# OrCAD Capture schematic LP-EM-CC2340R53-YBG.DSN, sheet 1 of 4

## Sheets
1 1_RF: size A3; title: LP-EM-CC2340R5-YBG
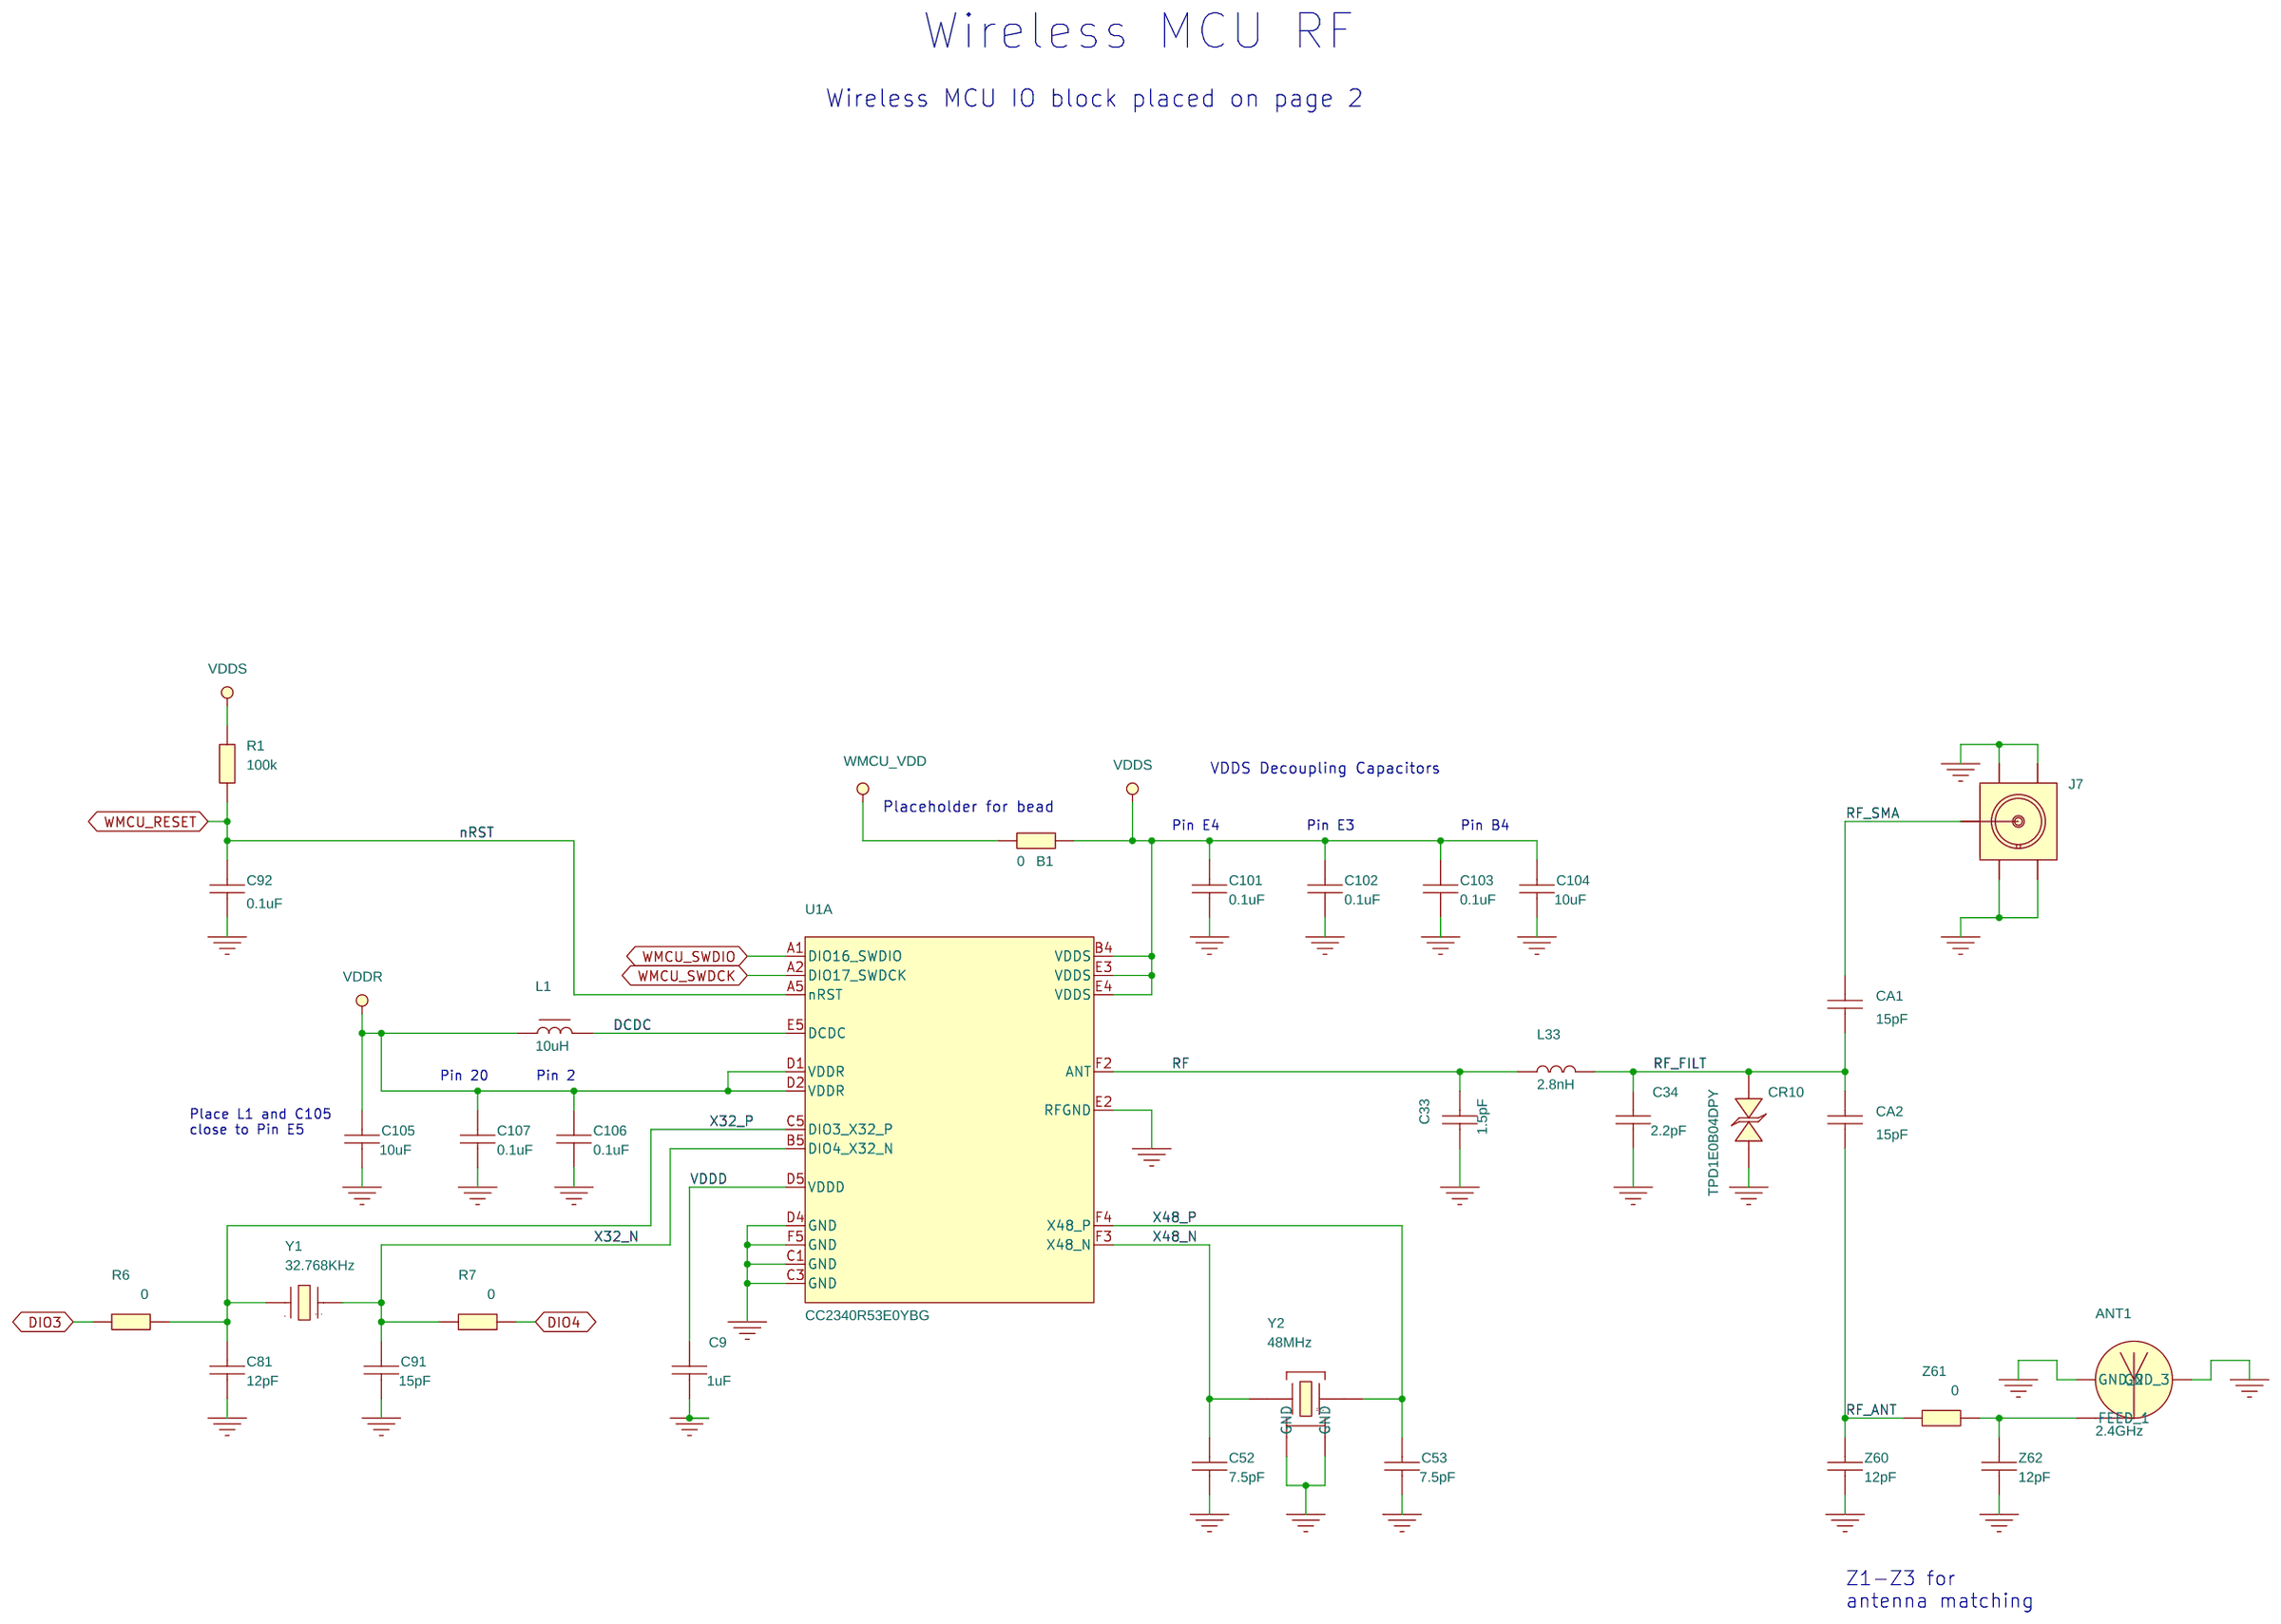
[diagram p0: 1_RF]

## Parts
sheet 1_RF
ANT1  2.4GHz  [ANTENNA_DN007AN]
B1  0  [RESC1608X55A2N]
C9  1uF  [CAPC1005X60B2N]
C33  1.5pF  [CAPC0603X35B2N]
C34  2.2pF  [CAPC0603X35B2N]
C52  7.5pF  [CAPC0603X35B2N]
C53  7.5pF  [CAPC0603X35B2N]
C81  12pF  [CAPC0603X35B2N]
C91  15pF  [CAPC0603X35B2N]
C92  0.1uF  [CAPC0603X35B2N]
C101  0.1uF  [CAPC0603X35B2N]
C102  0.1uF  [CAPC0603X35B2N]
C103  0.1uF  [CAPC0603X35B2N]
C104  10uF  [CAPC1608X100A2N]
C105  10uF  [CAPC1608X100A2N]
C106  0.1uF  [CAPC0603X35B2N]
C107  0.1uF  [CAPC0603X35B2N]
CA1  15pF  [CAPC0603X35B2N]
CA2  15pF  [CAPC0603X35B2N]
CR10  TPD1E0B04DPY  [SON65P100X60X45-2A2N]
J7  SMA-10V21-TGG  [HUSTSAN_SMA10V21TGGAN]
L1  10uH  [INDC1608X100A2N]
L33  2.8nH  [INDC0603X33A2N]
R1  100k  [RESC0603X35B2N]
R6  0  [RESC0603X35B2N]
R7  0  [RESC0603X35B2N]
Y1  32.768KHz  [XTAL_TZ3359DAAO73_A2N]
Y2  48MHz  [OSCCC205X165X50-4A2N]
Z60  12pF  [CAPC0603X35B2N]
Z61  0  [RESC0603X35B2N]
Z62  12pF  [CAPC0603X35B2N]
sheet 2_Peripherals
U1  CC2340R53E0YBG  [BGAFC28C40P260X219X50]  (sections A,B)

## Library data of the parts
ANT1 = ANTENNA_DN007: ANTENNA, NON COMPONENT, 2.4GHz INVERTED F ANTENNA, NOT APPLY; Additional Datasheet URL: https://www.ti.com/; AutoDoc File: http://notefied-dynamic-precision.com/DB/Apps/Desktop/Item/Object.aspx?id=85542; Budget Currency: N/A; Budget Price: N/A; CLASS: DISCRETE; Country of Origin: Missing Info; Datasheet URL: N/A; Datasheet URL 1: http://www.ti.com/lit/er/swrz002d/swrz002d.pdf; Datasheet URL 2: http://www.ti.com/lit/ds/symlink/cc2500.pdf; Definied Quality: INDUSTRIAL; Esd Level: HBM 500V; FPLIST: ANTENNA_DN007N,ANTENNA_DN007AN,; MPN: DN007; MPN Status: ACTIVE; MSL: N/A; MTBF: N/A; MTBF Standard: N/A; Manufacturer: TEXAS INSTRUMENTS; Mass: N/A; Max Oper Temp: +85DEGC; Maximum Operating Temperature: +85DEGC; Min Oper Temp: -40DEGC; Minimum Operating Temperature: -40DEGC; Mounting Type: NOT APPLY; NOTE Status: PREFERRED; NOTEfied URL: https://dev-webinterface.dpserver.no/item/7337272; Notes: Custom Item; Old Footprint: ANTENNA_DN007N,ANTENNA_DN007AN; Packing Size: N/A; Packing Type: Missing Info; Part Number: 13-00347; Part Type: Mechanic|ANTENNA|NON COMPONENT; ROHS: Not Applicable; Revision: R029; RoHS Status: LEADED; Status: Released; Texas Part Status: Under Review; Type: Mechanic; Vendor: TEXAS INSTRUMENTS; Vendor Part Number: DN007; Vendor Part Status: Active; WEIGHT: N/A
B1 = RESISTOR: RESISTOR, THICK FILM, JUMPER, 0, 0R/+0.05R, 1A, -55DEGC/+155DEGC, 0603, SMD; ALT_SYMBOLS: RESC1608X55A2L,RESC1608X55A2M; Additional Datasheet URL: https://www.koaspeer.com/products/resistors/general-purpose/rk73z/; Budgetary Price: .003 EUR; Country of Origin: China, Japan, Malaysia; Datasheet URL: https://www.koaspeer.com/pdfs/RK73Z.pdf; Lead Time: 46; Mass: 0.00214g; Maximum Operating Temperature: +155DEGC; Maximum Temperature Coefficient: N/A; Maximum Tolerance: +0.05R; Minimum Operating Temperature: -55DEGC; Minimum Temperature Coefficient: N/A; Minimum Temperature Coeficient: N/A; Minimum Tolerance: 0R; Mounting Type: SMD; NOTEfied URL: https://dev-webinterface.dpserver.no/item/7187910; PCB Package: 0603; Packing Size: 5000; Packing Type: Tape & Reel; Part Number: 01-01788; Part Type: Resistor|0603|JUMPER; ROHS: Exempt; Rated Current: 1A; Rated Power: 0.1; Rated Voltage: N/A; Resistor Type: THICK FILM; Revision: R048; Status: Released; Type: Resistor; Vendor: KOA SPEER; Vendor Part Number: RK73Z1JTTD; Vendor Part Status: Active
C9 = CAPACITOR: CAPACITOR, CERAMIC X7R, 1uF, 10V, -10%/+10%, -55DEGC/+125DEGC, 0402, SMD; ALT_SYMBOLS: CAPC1005X60A2L,CAPC1005X60A2M; Additional Datasheet URL: https://www.murata.com/en-us/products/productdetail?partno=GRM155Z71A105KE01%23; Budgetary Price: .01649 EUR; Country of Origin: China, Japan, Philippines, Singapore, Thailand; Datasheet URL: https://search.murata.co.jp/Ceramy/image/img/A01X/G101/ENG/GRM155Z71A105KE01-01A.pdf; Dielectric Type: X7R; Mass: 0.0016g; Maximum Operating Temperature: +125DEGC; Maximum Tolerance: +10%; Minimum Operating Temperature: -55DEGC; Minimum Tolerance: -10%; Mounting Type: SMD; NOTEfied URL: https://dev-webinterface.dpserver.no/item/34840285; PCB Package: 0402; Packing Size: 10000; Packing Type: Tape & Reel; Part Number: 02-10417; Part Type: Capacitor|CERAMIC|0402|STANDARD; REACH/SVHC Compliance: Compliant; REACH/SVHC Details: SVHC List Version Jul 08, 2021; REACH/SVHC Source: REACH Declaration; REACH/SVHC Status: Unaffected; ROHS: Compliant; Rated Voltage: 10V; Revision: R002; Status: Released; Texas Part Status: Under Review; Type: Capacitor; Vendor: MURATA; Vendor Part Number: GRM155Z71A105KE01D; Vendor Part Status: Active
C33 = CAPACITOR: CAPACITOR, CERAMIC C0G/NP0, 1.5pF, 50V, -0.1pF/+0.1pF, -55DEGC/+125DEGC, 0201, SMD; ALT_SYMBOLS: CAPC0603X35B2L,CAPC0603X35B2M; Additional Datasheet URL: https://www.murata.com/en-us/products/productdetail?partno=GRM0335C1H1R5BA01%23; AutoDoc File: https://notefied-dynamic-precision.com/DB/Apps/Desktop/Item/Object.aspx?id=113355; BU Name: TEXAS INSTRUMENTS NORWAY; Budget Currency: EUR; Budget Price: 0.006; Budgetary Price: .00272 USD; Country of Origin: China, Japan, Philippines; Datasheet URL: https://search.murata.co.jp/Ceramy/image/img/A01X/G101/ENG/GRM0335C1H1R5BA01-01A.pdf; Datasheet URL 1: http://psearch.murata.com/capacitor/product/GRM1555C1H1R0CA01%23.pdf; Datasheet URL 2: http://search.murata.co.jp/Ceramy/image/img/w_hinm/L0005E.pdf; Dielectric Type: C0G/NP0; Lead Time: 11; MPN: GRM1555C1H1R0CA01D; MPN Status: ACTIVE; Manufacturer: MURATA; Mass: 0.00033g; Max Oper Temp: +125DEGC; Max Tol: +0.25pF; Maximum Operating Temperature: +125DEGC; Maximum Tolerance: +0.1pF; Min Oper Temp: -55DEGC; Min Tol: -0.25pF; Minimum Operating Temperature: -55DEGC; Minimum Tolerance: -0.1pF; Mounting Type: SMD; NOTE Status: PREFERRED; NOTEfied URL: https://dev-webinterface.dpserver.no/item/7272572; Old Footprint: CAPC1005X60N; PCB Package: 0201; Packing Size: 50000; Packing Type: Tape & Reel; Part Number: 02-06129; Part Type: Capacitor|CERAMIC|0201|STANDARD; REACH/SVHC Compliance: Compliant; REACH/SVHC Details: SVHC List Version Jul 7, 2017; REACH/SVHC Source: REACH Declaration; REACH/SVHC Status: Unaffected; REACH/SVHC_COMPLIANCE: COMPLIANT; REACH/SVHC_DETAILS: SVHC LIST VERSION Dec 17, 2015; REACH/SVHC_SOURCE: REACH DECLARATION; REACH/SVHC_STATUS: UNAFFECTED; ROHS: Compliant; Rated Voltage: 50V; Revision: R027; RoHS Status: ROHS_COMPLIANT; Rtd Voltage: 50V; Status: Released; Texas Part Status: Under Review; Type: Capacitor; Vendor: MURATA; Vendor Part Number: GRM0335C1H1R5BA01J; Vendor Part Status: Active; WEIGHT: 0.0016g
C34 = CAPACITOR: CAPACITOR, CERAMIC C0G/NP0, 2.2pF, -0.1pF/+0.1pF, 50V, -55DEGC/+125DEGC, 0201, SMD; ALT_SYMBOLS: CAPC0603X35B2L,CAPC0603X35B2M; Additional Datasheet URL: https://pim.murata.com/en-us/pim/details?partNum=GRM0335C1H2R2BA01%23; Budgetary Price: .00272 USD; Country of Origin: China, Japan, Philippines, Singapore, Thailand; Datasheet URL: https://pim.murata.com/asset/pim4/ceramicCapacitorSMD/GRM0335C1H2R2BA01-01A-EN_PDF_CERAMICCAPACITORSMD?lastModifiedDatetime=20250813140605; Dielectric Type: C0G/NP0; Lead Time: 11; Mass: 0.00033g; Maximum Operating Temperature: +125DEGC; Maximum Tolerance: +0.1pF; Minimum Operating Temperature: -55DEGC; Minimum Tolerance: -0.1pF; Mounting Type: SMD; NOTEfied URL: https://webinterface.notefied-dynamic-precision.com/item/7272864; PCB Package: 0201; Packing Size: 50000; Packing Type: Tape & Reel; Part Number: 02-06136; Part Type: Capacitor|CERAMIC|0201|STANDARD; REACH/SVHC Compliance: Compliant; REACH/SVHC Details: SVHC List Version Jan 23, 2024 (240); REACH/SVHC Source: REACH Declaration; REACH/SVHC Status: Unaffected; ROHS: Compliant; Rated Voltage: 50V; Status: Released; Texas Part Status: Under Review; Type: Capacitor; Vendor: MURATA; Vendor Part Number: GRM0335C1H2R2BA01J; Vendor Part Status: Active
C52 C53 = CAPACITOR: CAPACITOR, CERAMIC C0G/NP0, 7.5pF, 50V, -0.1pF/+0.1pF, -55DEGC/+125DEGC, 0201, SMD; ALT_SYMBOLS: CAPC0603X35B2L,CAPC0603X35B2M; Additional Datasheet URL: https://www.murata.com/en-us/products/productdetail?partno=GRM0335C1H7R5BA01%23; Budgetary Price: .00221 USD; Country of Origin: China, Japan, Philippines; Datasheet URL: https://search.murata.co.jp/Ceramy/image/img/A01X/G101/ENG/GRM0335C1H7R5BA01-01A.pdf; Dielectric Type: C0G/NP0; Lead Time: 11; Mass: 0.00033g; Maximum Operating Temperature: +125DEGC; Maximum Tolerance: +0.1pF; Minimum Operating Temperature: -55DEGC; Minimum Tolerance: -0.1pF; Mounting Type: SMD; NOTEfied URL: https://dev-webinterface.dpserver.no/item/7272937; PCB Package: 0201; Packing Size: 50000; Packing Type: Tape & Reel; Part Number: 02-06189; Part Type: Capacitor|CERAMIC|0201|STANDARD; REACH/SVHC Compliance: Compliant; REACH/SVHC Details: SVHC List Version Jul 7, 2017; REACH/SVHC Source: REACH Declaration; REACH/SVHC Status: Unaffected; ROHS: Compliant; Rated Voltage: 50V; Revision: R027; Status: Released; Texas Part Status: Under Review; Type: Capacitor; Vendor: MURATA; Vendor Part Number: GRM0335C1H7R5BA01J; Vendor Part Status: Active
C81 = CAPACITOR: CAPACITOR, CERAMIC C0G/NP0, 12pF, 50V, -2%/+2%, -55DEGC/+125DEGC, 0201, SMD; ALT_SYMBOLS: CAPC0603X35B2L,CAPC0603X35B2M; Additional Datasheet URL: https://www.murata.com/en-us/products/productdetail?partno=GRM0335C1H120GA01%23; AutoDoc File: https://notefied-dynamic-precision.com/DB/Apps/Desktop/Item/Object.aspx?id=113345; BU Name: TEXAS INSTRUMENTS NORWAY; Budget Currency: EUR; Budget Price: 0.007; Budgetary Price: .00506 USD; Country of Origin: China, Japan, Philippines; Datasheet URL: https://search.murata.co.jp/Ceramy/image/img/A01X/G101/ENG/GRM0335C1H120GA01-01A.pdf; Datasheet URL 1: http://psearch.murata.com/capacitor/product/GRM1555C1H120JA01%23.pdf; Datasheet URL 2: http://search.murata.co.jp/Ceramy/image/img/w_hinm/L0005E.pdf; Definied Quality: INDUSTRIAL; Dielectric Type: C0G/NP0; Esd Level: N/A; Lead Time: 23; LifeCycle Status: ACTIVE; MPN: CAPACITOR_0402_12pF_C0G/NP0_M_+/-5%_50V; MPN Status: ACTIVE; MSL: N/A; MTBF: N/A; MTBF Standard: N/A; Manufacturer: MANUFACTURER SELECTION; Mass: 0.00033g; Max Oper Temp: +125DEGC; Max Tol: +5%; Maximum Operating Temperature: +125DEGC; Maximum Tolerance: +2%; Min Oper Temp: -55DEGC; Min Tol: -5%; Minimum Operating Temperature: -55DEGC; Minimum Tolerance: -2%; Mounting Type: SMD; NOTE Status: PREFERRED; NOTEfied URL: https://dev-webinterface.dpserver.no/item/31254676; Old Footprint: CAPC1005X60N; PCB Package: 0201; Packing Size: 15000; Packing Type: Tape & Reel; Part Number: 02-10307; Part Type: Capacitor|CERAMIC|0201|STANDARD; REACH/SVHC Compliance: Compliant; REACH/SVHC Details: SVHC List Version Jan 19, 2021; REACH/SVHC Source: REACH Declaration; REACH/SVHC Status: Unaffected; REACH/SVHC_COMPLIANCE: COMPLIANT; REACH/SVHC_DETAILS: SVHC LIST VERSION Dec 17, 2015; REACH/SVHC_SOURCE: REACH DECLARATION; REACH/SVHC_STATUS: UNAFFECTED; ROHS: Compliant; Rated Voltage: 50V; Revision: R003; RoHS Status: ROHS_COMPLIANT; Rtd Voltage: 50V; Status: Released; Texas Part Status: Under Review; Type: Capacitor; Vendor: MURATA; Vendor Part Number: GRM0335C1H120GA01D; Vendor Part Status: Active; WEIGHT: 0.0016g
C91 = CAPACITOR: CAPACITOR, CERAMIC C0G/NP0, 15pF, 50V, -2%/+2%, -55DEGC/+125DEGC, 0201, SMD; ALT_SYMBOLS: CAPC0603X35B2L,CAPC0603X35B2M; Additional Datasheet URL: https://www.murata.com/en-us/products/productdetail?partno=GRM0335C1H150GA01%23; AutoDoc File: https://notefied-dynamic-precision.com/DB/Apps/Desktop/Item/Object.aspx?id=114571; BU Name: TEXAS INSTRUMENTS NORWAY; Budget Currency: EUR; Budget Price: 0.006; Budgetary Price: .0032 USD; Client Status: UNDER_REVIEW; Country of Origin: China, Japan, Philippines; Datasheet URL: https://search.murata.co.jp/Ceramy/image/img/A01X/G101/ENG/GRM0335C1H150GA01-01A.pdf; Datasheet URL 1: http://psearch.murata.com/capacitor/product/GRM1555C1H150JA01%23.pdf; Datasheet URL 2: http://psearch.en.murata.com/capacitor/product/GRM1555C1H150JA01%23.html; Definied Quality: INDUSTRIAL; Dielectric Type: C0G/NP0; Esd Level: N/A; Lead Time: 11; LifeCycle Status: ACTIVE; MPN: CAPACITOR_0402_12pF_C0G/NP0_M_+/-5%_50V; MPN Status: ACTIVE; MSL: N/A; MTBF: N/A; MTBF Standard: N/A; Manufacturer: MANUFACTURER SELECTION; Mass: 0.00033g; Max Oper Temp: +125DEGC; Max Tol: +5%; Maximum Operating Temperature: +125DEGC; Maximum Tolerance: +2%; Min Oper Temp: -55DEGC; Min Tol: -5%; Minimum Operating Temperature: -55DEGC; Minimum Tolerance: -2%; Mounting Type: SMD; NOTE Status: PREFERRED; NOTEfied URL: https://dev-webinterface.dpserver.no/item/20744949; Old Footprint: CAPC1005X60N; PCB Package: 0201; Packing Size: 15000; Packing Type: Tape & Reel; Part Number: 02-09323; Part Type: Capacitor|CERAMIC|0201|STANDARD; REACH/SVHC Compliance: Compliant; REACH/SVHC Details: SVHC List Version Jan 15, 2019; REACH/SVHC Source: REACH Declaration; REACH/SVHC Status: Unaffected; REACH/SVHC_COMPLIANCE: COMPLIANT; REACH/SVHC_DETAILS: SVHC List Version Jan 12, 2017; REACH/SVHC_SOURCE: REACH DECLARATION; REACH/SVHC_STATUS: UNAFFECTED; ROHS: Compliant; Rated Voltage: 50V; Revision: R010; RoHS Status: ROHS_COMPLIANT; Rtd Voltage: 50V; Status: Released; Texas Part Status: Under Review; Type: Capacitor; Vendor: MURATA; Vendor Part Number: GRM0335C1H150GA01D; Vendor Part Status: Active; WEIGHT: 0.0016g
C92 C101-C103 C106 C107 = CAPACITOR: CAPACITOR, CERAMIC X7S, 0.1uF, 10V, -10%/+10%, -55DEGC/+125DEGC, 0201, SMD; ALT_SYMBOLS: CAPC0603X35B2L,CAPC0603X35B2M; Additional Datasheet URL: https://www.murata.com/en-us/products/productdetail?partno=GRM033C71A104KE14%23; AutoDoc File: https://notefied-dynamic-precision.com/DB/Apps/Desktop/Item/Object.aspx?id=115293; BU Name: TEXAS INSTRUMENTS NORWAY; Budgetary Price: .01328 USD; Client Status: UNDER_REVIEW; Country of Origin: China, Japan, Philippines, Singapore; Datasheet URL: https://search.murata.co.jp/Ceramy/image/img/A01X/G101/ENG/GRM033C71A104KE14-01A.pdf; Datasheet URL 1: http://psearch.en.murata.com/capacitor/product/GRM155R71E104KE14%23.pdf; Datasheet URL 2: http://search.murata.co.jp/Ceramy/image/img/w_hinm/L0005E.pdf; Dielectric Type: X7S; Lead Time: 23; LifeCycle Status: ACTIVE; MPN: GRM155R70J104KA01D; MPN Status: ACTIVE; Manufacturer: MURATA; Mass: 0.00033g; Max Oper Temp: +125DEGC; Max Tol: +10%; Maximum Operating Temperature: +125DEGC; Maximum Tolerance: +10%; Min Oper Temp: -55DEGC; Min Tol: -10%; Minimum Operating Temperature: -55DEGC; Minimum Tolerance: -10%; Mounting Type: SMD; NOTE Status: PREFERRED; NOTEfied URL: https://dev-webinterface.dpserver.no/item/31254761; Old Footprint: CAPC1005X60N,0402; PCB Package: 0201; Packing Size: 15000; Packing Type: Tape & Reel; Part Number: 02-10308; Part Type: Capacitor|CERAMIC|0201|STANDARD; REACH/SVHC Compliance: Compliant; REACH/SVHC Details: SVHC List Version Jan 19, 2021; REACH/SVHC Source: REACH Declaration; REACH/SVHC Status: Unaffected; REACH/SVHC_COMPLIANCE: COMPLIANT; REACH/SVHC_DETAILS: SVHC LIST VERSION Jun 20, 2016; REACH/SVHC_SOURCE: REACH DECLARATION; REACH/SVHC_STATUS: UNAFFECTED; ROHS: Compliant; Rated Voltage: 10V; Revision: R003; RoHS Status: ROHS_COMPLIANT; Rtd Voltage: 25V; Status: Released; Texas Part Status: Under Review; Type: Capacitor; Vendor: MURATA; Vendor Part Number: GRM033C71A104KE14D; Vendor Part Status: Active; WEIGHT: 0.0016g
C104 C105 = CAPACITOR: CAPACITOR, CERAMIC X7R, 10uF, 10V, -10%/+10%, -55DEGC/+125DEGC, 0603, SMD; ALT_SYMBOLS: CAPC1608X100A2L,CAPC1608X100A2M; Additional Datasheet URL: https://www.murata.com/en-us/products/productdetail?partno=GRM188Z71A106KA73%23; Budgetary Price: .05362 EUR; Country of Origin: China, Japan, Philippines; Datasheet URL: https://search.murata.co.jp/Ceramy/image/img/A01X/G101/ENG/GRM188Z71A106KA73-01A.pdf; Dielectric Type: X7R; Mass: 0.0091g; Maximum Operating Temperature: +125DEGC; Maximum Tolerance: +10%; Minimum Operating Temperature: -55DEGC; Minimum Tolerance: -10%; Mounting Type: SMD; NOTEfied URL: https://dev-webinterface.dpserver.no/item/34840340; PCB Package: 0603; Packing Size: 4000; Packing Type: Tape & Reel; Part Number: 02-10418; Part Type: Capacitor|CERAMIC|0603|STANDARD; REACH/SVHC Compliance: Compliant; REACH/SVHC Details: SVHC List Version Jul 08, 2021; REACH/SVHC Source: REACH Declaration; REACH/SVHC Status: Unaffected; ROHS: Compliant; Rated Voltage: 10V; Revision: R002; Status: Released; Texas Part Status: Under Review; Type: Capacitor; Vendor: MURATA; Vendor Part Number: GRM188Z71A106KA73D; Vendor Part Status: Active
CA1 CA2 = CAPACITOR: CAPACITOR, CERAMIC C0G/NP0, 15pF, 50V, -2%/+2%, -55DEGC/+125DEGC, 0201, SMD; ALT_SYMBOLS: CAPC0603X35B2L,CAPC0603X35B2M; Additional Datasheet URL: https://www.murata.com/en-us/products/productdetail?partno=GRM0335C1H150GA01%23; AutoDoc File: https://notefied-dynamic-precision.com/DB/Apps/Desktop/Item/Object.aspx?id=113345; BU Name: TEXAS INSTRUMENTS NORWAY; Budget Currency: EUR; Budget Price: 0.007; Budgetary Price: .0032 USD; Country of Origin: China, Japan, Philippines; Datasheet URL: https://search.murata.co.jp/Ceramy/image/img/A01X/G101/ENG/GRM0335C1H150GA01-01A.pdf; Datasheet URL 1: http://psearch.murata.com/capacitor/product/GRM1555C1H120JA01%23.pdf; Datasheet URL 2: http://search.murata.co.jp/Ceramy/image/img/w_hinm/L0005E.pdf; Definied Quality: INDUSTRIAL; Dielectric Type: C0G/NP0; Esd Level: N/A; Lead Time: 11; LifeCycle Status: ACTIVE; MPN: CAPACITOR_0402_12pF_C0G/NP0_M_+/-5%_50V; MPN Status: ACTIVE; MSL: N/A; MTBF: N/A; MTBF Standard: N/A; Manufacturer: MANUFACTURER SELECTION; Mass: 0.00033g; Max Oper Temp: +125DEGC; Max Tol: +5%; Maximum Operating Temperature: +125DEGC; Maximum Tolerance: +2%; Min Oper Temp: -55DEGC; Min Tol: -5%; Minimum Operating Temperature: -55DEGC; Minimum Tolerance: -2%; Mounting Type: SMD; NOTE Status: PREFERRED; NOTEfied URL: https://dev-webinterface.dpserver.no/item/20744949; Old Footprint: CAPC1005X60N; PCB Package: 0201; Packing Size: 15000; Packing Type: Tape & Reel; Part Number: 02-09323; Part Type: Capacitor|CERAMIC|0201|STANDARD; REACH/SVHC Compliance: Compliant; REACH/SVHC Details: SVHC List Version Jan 15, 2019; REACH/SVHC Source: REACH Declaration; REACH/SVHC Status: Unaffected; REACH/SVHC_COMPLIANCE: COMPLIANT; REACH/SVHC_DETAILS: SVHC LIST VERSION Dec 17, 2015; REACH/SVHC_SOURCE: REACH DECLARATION; REACH/SVHC_STATUS: UNAFFECTED; ROHS: Compliant; Rated Voltage: 50V; Revision: R010; RoHS Status: ROHS_COMPLIANT; Rtd Voltage: 50V; Status: Released; Texas Part Status: Under Review; Type: Capacitor; Vendor: MURATA; Vendor Part Number: GRM0335C1H150GA01D; Vendor Part Status: Active; WEIGHT: 0.0016g
CR10 = DIODE_TVS_BIDIR_S_0: DIODE, PROTECTION, TVS, BID, 6.7V, 15W, -40DEGC/+125DEGC, X1SON2, SMD; Additional Datasheet URL: https://www.ti.com/product/TPD1E0B04; AutoDoc File: https://notefied-dynamic-precision.com/DB/Apps/Desktop/Item/Object.aspx?id=118028; BU Name: DYNAMIC PRECISION GDANSK; Budget Currency: USD; Budget Price: 0.08; Budgetary Price: .144 USD; Client Status: UNDER_REVIEW; Country of Origin: China; Datasheet URL: https://www.ti.com/lit/gpn/TPD1E0B04; Datasheet URL 1: http://www.ti.com/lit/ds/symlink/tpd1e0b04.pdf; Datasheet URL 2: http://www.ti.com/lit/ml/mpss034c/mpss034c.pdf; Lead Time: 12; Mass: 0.0031g; Max Oper Temp: +125DEGC; Maximum Operating Temperature: +125DEGC; Min Oper Temp: -40DEGC; Minimum Operating Temperature: -40DEGC; Mounting Type: SMD; NOTEfied URL: https://dev-webinterface.dpserver.no/item/12481442; PCB Package: SON2; Packing Size: 10000; Packing Type: Tape & Reel; Part Number: 14-06704; Part Type: Diode|PROTECTION; REACH/SVHC Compliance: Compliant; REACH/SVHC Details: SVHC List Version Jan 12, 2017; REACH/SVHC Source: REACH Declaration; REACH/SVHC Status: Unaffected; ROHS: Compliant; Rated Power: 15W; Rated Voltage: 6.7V; Revision: R025; RoHS Status: ROHS_COMPLIANT; Rtd Power: 15W; Rtd Voltage: 6.7V; Status: Released; Texas Part Status: Under Review; Type: Diode; Vendor: TEXAS INSTRUMENTS; Vendor Part Number: TPD1E0B04DPYR; Vendor Part Status: Active; Weight: 0.0031g
J7 = CONN_COAX_1_4: CONNECTOR, COAX, RF, FEMALE, STRAIGHT, 1 PIN(S), SMD; ALT_SYMBOLS: HUSTSAN_SMA10V21TGGL,HUSTSAN_SMA10V21TGGM; Additional Datasheet URL: http://www.hustsan.com.tw/cgi-bin/productfn/pdt_detail_lst.pl?ProdID=143; AutoDoc File: https://notefied-dynamic-precision.com/DB/Apps/Desktop/Item/Object.aspx?id=84956; BU Name: DYNAMIC PRECISION GDANSK; Budget Currency: N/A; Budget Price: N/A; Client Status: UNDER_REVIEW; Country of Origin: Missing Info; Datasheet URL: http://www.hustsan.com.tw/uploaddir/product/SMA-10V21.pdf; Datasheet URL 1: http://www.hustsan.com.tw/uploaddir/product/SMA-10V21.pdf; Datasheet URL 2: http://www.hustsan.com.tw/cgi-bin/productfn/pdt_detail_lst.pl?ProdID=143; FPLIST: HUSTSAN_SMA10V21TGGAN,HUSTSAN_SMA10V21TGGN; Mass: N/A; Mounting Type: SMD; NOTEfied URL: https://dev-webinterface.dpserver.no/item/7315189; No Of Pos: 1; Number of Positions: 1; Packing Size: 350; Packing Type: Tape & Reel; Part Number: 06-02188; Part Type: Connector|COAX|RF; REACH/SVHC Compliance: Compliant; REACH/SVHC Details: SVHC List Version Jun 20, 2016; REACH/SVHC Source: REACH Declaration; REACH/SVHC Status: Unaffected; REACH/SVHC_COMPLIANCE: COMPLIANT; REACH/SVHC_DETAILS: SVHC LIST VERSION Jan 12, 2016; REACH/SVHC_SOURCE: REACH DECLARATION; REACH/SVHC_STATUS: UNAFFECTED; ROHS: Compliant; Revision: R024; RoHS Status: ROHS_COMPLIANT; Status: Released; Texas Part Status: Under Review; Type: Connector; Vendor: HUS-TSAN; Vendor Part Status: Active; Weight: N/A
L1 = IND_CORE: INDUCTOR, STANDARD, CHIP, FERRITE CORE, 10uH, -20%/+20%, 0.1A, -55DEGC/+125DEGC, 0603, SMD; ALT_SYMBOLS: INDC1608X100A2L,INDC1608X100A2M; Additional Datasheet URL: https://www.murata.com/en-us/products/productdetail?partno=LQM18DN100M70%23; Budgetary Price: .02994 USD; Country of Origin: Missing Info; Datasheet URL: https://search.murata.co.jp/Ceramy/image/img/P02/JELF243B-0086.pdf; Frequency: 32MHz; Mass: 0.005g; Maximum Operating Temperature: +125DEGC; Maximum Tolerance: +20%; Minimum Operating Temperature: -55DEGC; Minimum Tolerance: -20%; Mounting Type: SMD; NOTEfied URL: https://dev-webinterface.dpserver.no/item/34987006; PCB Package: 0603; Packing Size: 4000; Packing Type: Tape & Reel; Part Number: 03-08367; Part Type: Inductor|STANDARD|CHIP|0603; REACH/SVHC Compliance: Missing Info; REACH/SVHC Details: Jul 08, 2021 (219); REACH/SVHC Source: N/A; REACH/SVHC Status: Unaffected; ROHS: Compliant; Rated Current: 0.1A; Resistance: 1.05; Revision: R002; Status: Released; Texas Part Status: Under Review; Type: Inductor; Vendor: MURATA; Vendor Part Number: LQM18DN100M70L; Vendor Part Status: Active
L33 = INDUCTOR: INDUCTOR, RF, CHIP, NON-MAGNETIC CORE, 2.8nH, -0.1nH/+0.1nH, 0.5A, -55DEGC/+125DEGC, 0201, SMD; ALT_SYMBOLS: INDC0603X33A2L,INDC0603X33A2M; Additional Datasheet URL: https://www.murata.com/en-us/products/productdetail?partno=LQP03TN2N8B02%23; Country of Origin: Missing Info; Datasheet URL: https://search.murata.co.jp/Ceramy/image/img/P02/JELF243C-0015.pdf; Frequency: 9.5GHz; Mass: 0.0002g; Maximum Operating Temperature: +125DEGC; Maximum Tolerance: +0.1nH; Minimum Operating Temperature: -55DEGC; Minimum Tolerance: -0.1nH; Mounting Type: SMD; NOTEfied URL: https://dev-webinterface.dpserver.no/item/7300385; PCB Package: 0201; Packing Size: 50000; Packing Type: Tape & Reel; Part Number: 03-06931; Part Type: Inductor|RF|CHIP|0201; ROHS: Compliant; Rated Current: 0.5A; Resistance: 0.2; Revision: R022; Status: Released; Texas Part Status: Under Review; Type: Inductor; Vendor: MURATA; Vendor Part Number: LQP03TN2N8B02J; Vendor Part Status: Active
R1 = RESISTOR: RESISTOR, THICK FILM, 100k, -5%/+5%, 0.05W, 30V, -55DEGC/+155DEGC, 0201, SMD; ALT_SYMBOLS: RESC0603X35B2L,RESC0603X35B2M; Additional Datasheet URL: https://www.vishay.com/en/product/20052/; Budgetary Price: .005 EUR; Country of Origin: China, Israel, Taiwan; Datasheet URL: https://www.vishay.com/docs/20052/crcw0201e3.pdf; Lead Time: 20; Mass: 0.00017g; Maximum Operating Temperature: +155DEGC; Maximum Temperature Coefficient: +200PPM/DEGC; Maximum Tolerance: +5%; Minimum Operating Temperature: -55DEGC; Minimum Temperature Coefficient: -200PPM/DEGC; Minimum Temperature Coeficient: -200PPM/DEGC; Minimum Tolerance: -5%; Mounting Type: SMD; NOTEfied URL: https://dev-webinterface.dpserver.no/item/7195810; PCB Package: 0201; Packing Size: 10000; Packing Type: Tape & Reel; Part Number: 01-04220; Part Type: Resistor|0201|STANDARD; REACH/SVHC Compliance: Compliant; REACH/SVHC Details: SVHC List Version Dec 17, 2015; REACH/SVHC Source: Material Declaration; REACH/SVHC Status: Unaffected; ROHS: Exempt; Rated Current: N/A; Rated Power: 0.05W; Rated Voltage: 30V; Resistor Type: THICK FILM; Revision: R008; Status: Released; Texas Part Number: TEXAS_00013; Texas Part Status: Under Review; Type: Resistor; Vendor: VISHAY; Vendor Part Number: CRCW0201100KJNED; Vendor Part Status: Active
R6 R7 Z61 = RESISTOR: RESISTOR, THICK FILM, JUMPER, 0, 0R/+0.05R, 0.5A, -55DEGC/+125DEGC, 0201, SMD; ALT_SYMBOLS: RESC0603X35B2L,RESC0603X35B2M; Additional Datasheet URL: https://www.koaspeer.com/products/resistors/general-purpose/rk73z/; Budgetary Price: .012 EUR; Country of Origin: Missing Info; Datasheet URL: https://www.koaspeer.com/pdfs/RK73Z.pdf; Lead Time: 14; Mass: 0.00014g; Maximum Operating Temperature: +125DEGC; Maximum Temperature Coefficient: N/A; Maximum Tolerance: +0.05R; Minimum Operating Temperature: -55DEGC; Minimum Temperature Coefficient: N/A; Minimum Temperature Coeficient: N/A; Minimum Tolerance: 0R; Mounting Type: SMD; NOTEfied URL: https://dev-webinterface.dpserver.no/item/7239994; PCB Package: 0201; Packing Size: 10000; Packing Type: Tape & Reel; Part Number: 01-18293; Part Type: Resistor|0201|JUMPER; ROHS: Exempt; Rated Current: 0.5A; Rated Power: N/A; Rated Voltage: N/A; Resistor Type: THICK FILM; Revision: R013; Status: Released; Type: Resistor; Vendor: KOA SPEER; Vendor Part Number: RK73Z1HTTC; Vendor Part Status: NRND
Y1 = XTAL: CRYSTAL, RESONATOR, 32.768KHz, -380PPM/+380PPM, -40DEGC/+125DEGC, SMD; ALT_SYMBOLS: XTAL_TZ3359DAAO73_A2L,XTAL_TZ3359DAAO73_A2M; Additional Datasheet URL: https://www.taisaw.com/products/searchA?param=TZ3359DAAO73; Capacitance: 7pF; Country of Origin: Missing Info; Datasheet URL: https://www.taisaw.com/assets/PDF/TZ3359DAAO73%20_Rev.1.pdf; Maximum Operating Temperature: +125DEGC; Maximum Stability: +380PPM; Maximum Tolerance: +20PPM; Minimum Operating Temperature: -40DEGC; Minimum Stability: -380PPM; Minimum Tolerance: -20PPM; Mounting Type: SMD; NOTEfied URL: https://dev-webinterface.dpserver.no/item/34987642; Notes: Non-standard part/non-catalogue part. Created on the basis of documentation provided by the customer (Texas Instruments).; Packing Size: 5000; Packing Type: Tape & Reel; Part Number: 12-01593; Part Type: Crystal|RESONATOR; REACH/SVHC Compliance: Missing Info; REACH/SVHC Details: N/A; REACH/SVHC Source: N/A; REACH/SVHC Status: Missing Info; ROHS: Compliant; Revision: R001; Status: Released; Texas Part Status: Under Review; Type: Crystal; Vendor: TAI-SAW; Vendor Part Number: TZ3359DAAO73; Vendor Part Status: Active
Y2 = XTAL_4PINS_1_3: CRYSTAL, RESONATOR, 48MHz, -30PPM/+30PPM, -40DEGC/+125DEGC, SMD; ALT_SYMBOLS: OSCCC205X165X50-4A2L,OSCCC205X165X50-4A2M; Additional Datasheet URL: https://www.taisaw.com/products-search-a?param=TZ3908AAAO43; Capacitance: 7pF; Country of Origin: Missing Info; Datasheet URL: https://www.taisaw.com/assets/PDF/TZ3908AAAO43%20_Rev%203.pdf; Mass: 0.0057g; Maximum Operating Temperature: +125DEGC; Maximum Stability: +30PPM; Maximum Tolerance: +5PPM; Minimum Operating Temperature: -40DEGC; Minimum Stability: -30PPM; Minimum Tolerance: -5PPM; Mounting Type: SMD; NOTEfied URL: https://dev-webinterface.dpserver.no/item/34987535; Notes: Non-standard part/non-catalogue part. Created on the basis of documentation provided by the customer (Texas Instruments).; Packing Size: 3000; Packing Type: Tape & Reel; Part Number: 12-01592; Part Type: Crystal|RESONATOR; REACH/SVHC Compliance: Missing Info; REACH/SVHC Details: N/A; REACH/SVHC Source: N/A; REACH/SVHC Status: Missing Info; ROHS: Compliant; Revision: R001; Status: Released; Texas Part Status: Under Review; Type: Crystal; Vendor: TAI-SAW; Vendor Part Number: TZ3908AAAO43; Vendor Part Status: Active
Z60 Z62 = CAPACITOR: CAPACITOR, CERAMIC C0G/NP0, 12pF, 50V, -2%/+2%, -55DEGC/+125DEGC, 0201, SMD; ALT_SYMBOLS: CAPC0603X35B2L,CAPC0603X35B2M; Additional Datasheet URL: https://www.murata.com/en-us/products/productdetail?partno=GRM0335C1H120GA01%23; AutoDoc File: https://notefied-dynamic-precision.com/DB/Apps/Desktop/Item/Object.aspx?id=113344; BU Name: TEXAS INSTRUMENTS NORWAY; Budget Currency: USD; Budget Price: 0.00589; Budgetary Price: .00506 USD; Country of Origin: China, Japan, Philippines; Datasheet URL: https://search.murata.co.jp/Ceramy/image/img/A01X/G101/ENG/GRM0335C1H120GA01-01A.pdf; Datasheet URL 1: N/A; Datasheet URL 2: N/A; Dielectric Type: C0G/NP0; Lead Time: 23; MPN: CAPACITOR_0402_DNM_N/A_M; MPN Status: ACTIVE; Manufacturer: Manufacturer selection; Mass: 0.00033g; Max Oper Temp: +125DEGC; Maximum Operating Temperature: +125DEGC; Maximum Tolerance: +2%; Min Oper Temp: -55DEGC; Minimum Operating Temperature: -55DEGC; Minimum Tolerance: -2%; Mounting Type: SMD; NOTE Status: PREFERRED; NOTEfied URL: https://dev-webinterface.dpserver.no/item/31254676; Old Footprint: CAPC1005X60N; PCB Package: 0201; Packing Size: 15000; Packing Type: Tape & Reel; Part Number: 02-10307; Part Type: Capacitor|CERAMIC|0201|STANDARD; REACH/SVHC Compliance: Compliant; REACH/SVHC Details: SVHC List Version Jan 19, 2021; REACH/SVHC Source: REACH Declaration; REACH/SVHC Status: Unaffected; ROHS: Compliant; Rated Voltage: 50V; Revision: R003; RoHS Status: MISSING_INFO; Status: Released; Texas Part Status: Under Review; Type: Capacitor; Vendor: MURATA; Vendor Part Number: GRM0335C1H120GA01D; Vendor Part Status: Active; Weight: N/A
U1 = IC_CC2340R5_DSBGA28_V1: IC, MICROCONTROLLER, CC2340R5, 32-bit, SIMPLELINK WIRELESS MCU ARM CORTEX -M0+, 512kbyte FLASH, 36kbyte SRAM, 12kbyte ROM, 1.71V TO 3.8V, DSBGA28, SMD; Additional Datasheet URL: https://www.ti.com/product/CC2340R5; Country of Origin: Missing Info; Datasheet URL: https://www.ti.com/lit/ds/symlink/cc2340r5.pdf; Frequency: 48MHz; Mass: N/A; Maximum Operating Temperature: +125DEGC; Minimum Operating Temperature: -40DEGC; Mounting Type: SMD; NOTEfied URL: https://dev-webinterface.dpserver.no/item/56099855; Notes: Pre-production version of CC2340R5 packaged in DSBGA28, not available publicly.; PCB Package: DSBGA28; Packing Size: N/A; Packing Type: Missing Info; Part Number: 18-38943; Part Type: IC|MICROCONTROLLER|TEXAS INSTRUMENTS; ROHS: Missing Info; Rated Voltage: 1.71V TO 3.8V; Status: Released; Texas Part Status: Under Review; Type: IC; Vendor: TEXAS INSTRUMENTS; Vendor Part Status: Preliminary

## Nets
GND: ANT1.2(GND) ANT1.3(GND) C9.2 C33.1 C34.2 C52.2 C53.2 C81.2 C91.2 C92.2 C101.2 C102.2 C103.2 C104.2 C105.2 C106.2 C107.2 CR10.1 J7.2 J7.3 J7.4 J7.5 U1.C1(GND) U1.C3(GND) U1.D4(GND) U1.E2(RFGND) U1.F5(GND) Y2.2(GND) Y2.4(GND) Z60.2 Z62.2 ; also on sheet 2 3 4
VDDD: C9.1 U1.D5(VDDD)
VDDR: C105.1 C106.1 C107.1 L1.1 U1.D1(VDDR) U1.D2(VDDR)
VDDS: B1.1 C101.1 C102.1 C103.1 C104.1 R1.2 U1.B4(VDDS) U1.E3(VDDS) U1.E4(VDDS)
DCDC: L1.2 U1.E5(DCDC)
DIO3: R6.2 ; also on sheet 2
DIO4: R7.1 ; also on sheet 2
RF: C33.2 L33.1 U1.F2(ANT)
RF_ANT: CA2.1 Z60.1 Z61.2
RF_FILT: C34.1 CA1.1 CA2.2 CR10.2 L33.2
RF_SMA: CA1.2 J7.1
WMCU_RESET: C92.1 R1.1 U1.A5(nRST) ; also on sheet 2 3
WMCU_SWDCK: U1.A2(DIO17_SWDCK) ; also on sheet 2 3
WMCU_SWDIO: U1.A1(DIO16_SWDIO) ; also on sheet 2 3
WMCU_VDD: B1.2 ; also on sheet 2 3
X32_N: C91.1 R7.2 U1.B5(DIO4_X32_N) Y1.2
X32_P: C81.1 R6.1 U1.C5(DIO3_X32_P) Y1.1
X48_N: C52.1 U1.F3(X48_N) Y2.1
X48_P: C53.1 U1.F4(X48_P) Y2.3
N3377070: ANT1.1(FEED) Z61.1 Z62.1

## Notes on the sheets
sheet 1
- Wireless MCU RF
- Wireless MCU IO block placed on page 2
- VDDS Decoupling Capacitors
- Placeholder for bead
- Pin E4
- Pin E3
- Pin B4
- Pin 20
- Pin 2
- Place L1 and C105
  close to Pin E5
- Z1-Z3 for
  antenna matching
